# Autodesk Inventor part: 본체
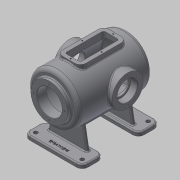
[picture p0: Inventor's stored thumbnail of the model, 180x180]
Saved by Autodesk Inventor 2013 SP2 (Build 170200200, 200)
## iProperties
Created: 2016-02
Part Number: 본체
Material: 일반
Document SubType Name: Modeling
Designer: mduedu
Density: 1 g/cm^3
Author: mduedu
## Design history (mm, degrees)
sketch "스케치2"
  geometry: L1 (0, 100)-(0, -100); L2 (65, -87.083)-(65, 100); L3 (65, 100)-(0, 100); A1 r 170 centre (0, 70) between (0, -100) and (65, -87.083); 2 further points
  constraints: 6 end point, 2 point on circle, 1 centre point, 1 coincident, 1 horizontal, 1 midpoint, 1 parallel, 1 point on line, 1 vertical
  dimensions: "d3" = 200 distance of L1.start L1.end; "d5" = 130 diameter of L2 L1; "d6" = 170 radius of A1
revolve "회전1" sketch "스케치2" stored, may be unused: angle "d7" = 90 deg
sketch "스케치3"
  geometry: C1 r 47.5 at (0, 0); 1 further point
  constraints: 1 centre point, 1 coincident
  dimensions: "d8" = 95 diameter of C1
extrude "돌출2" join sketch "스케치3" distance "d10" = 10; taper "d11" = 0 deg
sketch "스케치5"
  geometry: L1 (47.5, 110)-(47.5, 100) reference; L2 (47.5, 100)-(65, 100) reference; L3 (65, 100)-(65, -87.083) reference; L4 (-65, -87.083)-(-65, 100) reference; L5 (-65, 100)-(-47.5, 100) reference; L6 (-47.5, 100)-(-47.5, 110) reference; L7 (-47.5, 110)-(47.5, 110) reference; L8 (55, 85)-(55, -80.25); L9 (0, 85)-(55, 85); L10 (0, 85)-(0, -90); A1 r 170 centre (0, 70) between (-65, -87.083) and (0, -100) reference; A2 r 170 centre (0, 70) between (0, -100) and (65, -87.083) reference; A3 r 160 centre (0, 70) between (0, -90) and (55, -80.25); 1 further point
  constraints: 6 end point, 2 point on circle, 1 centre point, 1 parallel, 1 perpendicular, 1 point on line, 1 vertical
  dimensions: "d13" = 10 distance between parallel lines of L3 L8; "d14" = 10 radial gap between concentric circles of A3 A1; "d15" = 15 distance between parallel lines of L9 L2
revolve "회전2" sketch "스케치5" stored, may be unused: angle "d16" = 90 deg
hole "구멍1" diameter "d19" = 65; stored, may be unused: countersink angle "d23" = 90 deg, drill point angle "d25" = 118 deg; dims "d17" = 10, "d18" = 10, "d20" = 6, "d21" = 4, "d22" = 2, "d24" = 8
node "작업 평면1"
sketch "스케치6"
  geometry: L1 (47.5, 110)-(-47.5, 110) reference; C1 r 40 at (0, -17); 1 further point
  constraints: 1 centre point, 1 vertical alignment
  dimensions: "d27" = 80 diameter of C1; "d29" = 127 distance from line of C1.centre L1
extrude "돌출3" join sketch "스케치6" stored distance "d30" = 10; taper "d31" = 0 deg
hole "구멍2" diameter "d34" = 42; stored, may be unused: countersink angle "d38" = 90 deg, drill point angle "d40" = 118 deg; dims "d32" = 10, "d33" = 10, "d35" = 6, "d36" = 52, "d37" = 18, "d39" = 8
sketch "스케치7" dims "d41" = 65
  geometry: C1 r 40 at (0, 0) reference; 3 further points
  constraints: 2 vertical alignment, 1 coincident, 2 other
hole "구멍3" sketch "스케치7" at (0, 32.5) diameter "d43" = 3.242; stored, may be unused: countersink angle "d47" = 90 deg, drill point angle "d49" = 118 deg; dims "d44" = 11, "d45" = 13, "d46" = 18, "d48" = 13
sketch "스케치8" dims "d53" = 80
  geometry: 3 further points
  constraints: 2 vertical alignment, 1 coincident, 2 other
hole "구멍4" sketch "스케치8" at (0, 40) diameter "d56" = 3.242; stored, may be unused: countersink angle "d60" = 90 deg, drill point angle "d62" = 118 deg; dims "d57" = 11, "d58" = 13, "d59" = 18, "d61" = 13
fillet "모깎기1" dims "d66" = 10
fillet "모깎기2" dims "d67" = 3
fillet "모깎기3" dims "d68" = 0.3
chamfer "모따기1" distance "d69" = 1; stored, may be unused: second distance "d70" = 2, angle "d71" = 45 deg
node "작업 평면2"
sketch "스케치9"
  geometry: L1 (75, 100)-(-75, 100); L2 (-75, 100)-(-75, -100); L3 (-75, -100)-(75, -100); L4 (75, -100)-(75, 100); 1 further point
  constraints: 8 end point, 2 parallel, 1 horizontal, 1 perpendicular
  dimensions: "d73" = 200 distance of L3.end L1.start; "d75" = 150 distance of L2.end L3.end; "d76" = 100 distance from line of L1 point (0, 0); "d77" = 75 distance from line of L4 point (0, 0)
extrude "돌출4" join sketch "스케치9" distance "d78" = 10; taper "d79" = 0 deg
sketch "스케치10"
  geometry: L1 (-75, -100)-(75, -100) reference; L2 (75, 100)-(-75, 100) reference; L3 (0, -100)-(0, 100); L4 (-75, 100)-(-75, -100) reference; L5 (75, -100)-(75, 100) reference; L6 (-75, 0)-(75, 0); L7 (-50, -63)-(50, -63); L8 (50, -63)-(50, -55); L9 (50, -55)-(-50, -55); L10 (-50, -55)-(-50, -63); L11 (-50, 63)-(50, 63); L12 (50, 63)-(50, 55); L13 (50, 55)-(-50, 55); L14 (-50, 55)-(-50, 63); 1 further point
  constraints: 20 end point, 4 midpoint, 4 symmetric about line, 2 parallel, 1 horizontal, 1 perpendicular, 1 other
  dimensions: "d80" = 8 distance of L9.end L7.start; "d82" = 100 distance of L7.start L7.end; "d83" = 55 distance between parallel lines of L9 L6
extrude "돌출5" join sketch "스케치10" stored distance "d84" = 10; taper "d85" = 0 deg
feature "면 기울기1" dims angle "d86" = 10 deg
sketch "스케치11"
  geometry: L1 (-110, 55)-(-51.482, 55) reference; L2 (-110, -55)-(-51.482, -55) reference; L3 (-95, 55)-(-95, -55); L4 (-65, 90)-(-65, -80.25) reference; 1 further point
  constraints: 2 end point, 2 point on line, 1 perpendicular
  dimensions: "d87" = 30 distance between parallel lines of L3 L4
feature "리브1" sketch "스케치11" dims "d88" = 1, "d89" = 8, "d90" = 0, "d91" = 0, "d92" = 1, "d93" = 1
sketch "스케치12"
  geometry: L1 (-110, 55)-(-51.482, 55) reference; L2 (-110, -55)-(-51.482, -55) reference; L3 (-110, 100)-(-110, -100) reference; L4 (-120, 152)-(-120, -142) reference; L5 (-110, 45)-(-120, 45); L6 (-120, 45)-(-120, -45); L7 (-120, -45)-(-110, -45); L8 (-110, -45)-(-110, 45); 1 further point
  constraints: 8 end point, 2 parallel, 2 point on line, 1 horizontal, 1 perpendicular
  dimensions: "d94" = 10 distance between parallel lines of L7 L2; "d95" = 10 distance between parallel lines of L1 L5
extrude "돌출6" cut sketch "스케치12" stored distance "d96" = 10; taper "d97" = 0 deg
fillet "모깎기4" dims "d98" = 15
sketch "스케치13"
  geometry: C1 r 5 at (-60, -85); C2 r 5 at (60, -85); C3 r 5 at (60, 85); C4 r 5 at (-60, 85); A1 r 15 centre (-60, -85) between (-75, -85) and (-60, -100) reference; A2 r 15 centre (60, -85) between (60, -100) and (75, -85) reference; A3 r 15 centre (60, 85) between (75, 85) and (60, 100) reference; A4 r 15 centre (-60, 85) between (-60, 100) and (-75, 85) reference; 1 further point
  constraints: 4 centre point, 4 coincident, 3 equal radius
  dimensions: "d99" = 10 diameter of C1
extrude "돌출7" cut sketch "스케치13" stored distance "d101" = 10; taper "d102" = 0 deg
fillet "모깎기5" dims "d103" = 3, "d104" = 3
fillet "모깎기6" dims "d105" = 3
sketch "스케치14"
  geometry: L1 (-60, -100)-(60, -100) reference; 2 further points
  constraints: 1 vertical alignment, 1 other
  dimensions: "d106" = 15 distance from line of point (0, -85) L1
feature "엠보싱1" sketch "스케치14" dims "d3" = 200, "d5" = 130, "d6" = 170, "d14" = 10, "d107" = 0.5, "d108" = 0
node "작업 평면3"
sketch "스케치15"
  geometry: L1 (-30, 60)-(30, 60); L2 (30, 60)-(30, -60); L3 (30, -60)-(-30, -60); L4 (-30, -60)-(-30, 60); 2 further points
  constraints: 8 end point, 2 parallel, 1 horizontal, 1 midpoint, 1 perpendicular, 1 vertical alignment
  dimensions: "d110" = 60 distance of L2.end L3.end; "d112" = 60 distance from line of L3 point (0, 0); "d113" = 120 distance of L1.end L2.end
extrude "돌출8" join sketch "스케치15" stored distance "d114" = 10; taper "d115" = 0 deg
fillet "모깎기7" dims "d116" = 15
sketch "스케치16"
  geometry: L1 (-30, -45)-(-30, 45) reference; L2 (-15, 60)-(15, 60) reference; L3 (30, 45)-(30, -45) reference; L4 (15, -60)-(-15, -60) reference; L5 (15, 50)-(-15, 50); L6 (-20, 45)-(-20, -45); L7 (-15, -50)-(15, -50); L8 (20, -45)-(20, 45); A1 r 15 centre (-15, -45) between (-30, -45) and (-15, -60) reference; A2 r 15 centre (-15, 45) between (-15, 60) and (-30, 45) reference; A3 r 15 centre (15, 45) between (30, 45) and (15, 60) reference; A4 r 15 centre (15, -45) between (15, -60) and (30, -45) reference; A5 r 5 centre (-15, 45) between (-15, 50) and (-20, 45); A6 r 5 centre (-15, -45) between (-20, -45) and (-15, -50); A7 r 5 centre (15, -45) between (15, -50) and (20, -45); A8 r 5 centre (15, 45) between (20, 45) and (15, 50); 1 further point
  constraints: 8 end point, 8 point on circle, 4 centre point, 7 other
  dimensions: "d117" = 10 distance between parallel lines of L6 L1
extrude "돌출9" cut sketch "스케치16" stored distance "d118" = 10; taper "d119" = 0 deg
fillet "모깎기8" dims "d120" = 3
sketch "스케치17"
  geometry: L1 (-30, -45)-(-30, 45) reference; L2 (-15, 60)-(15, 60) reference; L3 (30, 45)-(30, -45) reference; L4 (15, -60)-(-15, -60) reference; L5 (20, -45)-(20, 45) reference; L6 (15, 50)-(-15, 50) reference; L7 (-20, 45)-(-20, -45) reference; L8 (-15, -50)-(15, -50) reference; L9 (15, 55)-(-15, 55); L10 (-25, 45)-(-25, -45); L11 (-15, -55)-(15, -55); L12 (25, -45)-(25, 45); A1 r 15 centre (-15, 45) between (-15, 60) and (-30, 45) reference; A2 r 15 centre (15, 45) between (30, 45) and (15, 60) reference; A3 r 15 centre (15, -45) between (15, -60) and (30, -45) reference; A4 r 15 centre (-15, -45) between (-30, -45) and (-15, -60) reference; A5 r 5 centre (15, -45) between (15, -50) and (20, -45) reference; A6 r 5 centre (15, 45) between (20, 45) and (15, 50) reference; A7 r 5 centre (-15, 45) between (-15, 50) and (-20, 45) reference; A8 r 5 centre (-15, -45) between (-20, -45) and (-15, -50) reference; A9 r 10 centre (-15, 45) between (-15, 55) and (-25, 45); A10 r 10 centre (-15, -45) between (-25, -45) and (-15, -55); A11 r 10 centre (15, -45) between (15, -55) and (25, -45); A12 r 10 centre (15, 45) between (25, 45) and (15, 55); 5 further points
  constraints: 8 end point, 8 point on circle, 4 centre point, 4 midpoint, 7 other
  dimensions: "d121" = 5 distance between parallel lines of L10 L1
hole "구멍5" sketch "스케치17" at (0, 55), (25, 0), (0, -55), (-25, 0) diameter "d122" = 3.242; stored, may be unused: countersink angle "d126" = 90 deg, drill point angle "d128" = 118 deg; dims "d123" = 9, "d124" = 13, "d125" = 18, "d127" = 11
fillet "모깎기9" dims "d129" = 3
node "솔리드2"
pattern_circular "원형 패턴1" dims angle "d51" = 360 deg
mirror "대칭1"
pattern_circular "원형 패턴2" dims angle "d64" = 360 deg
node "절단 모서리 투영1"
node "절단 모서리 투영2"
node "절단 모서리 투영3"
other parameters: "d26" = 75
